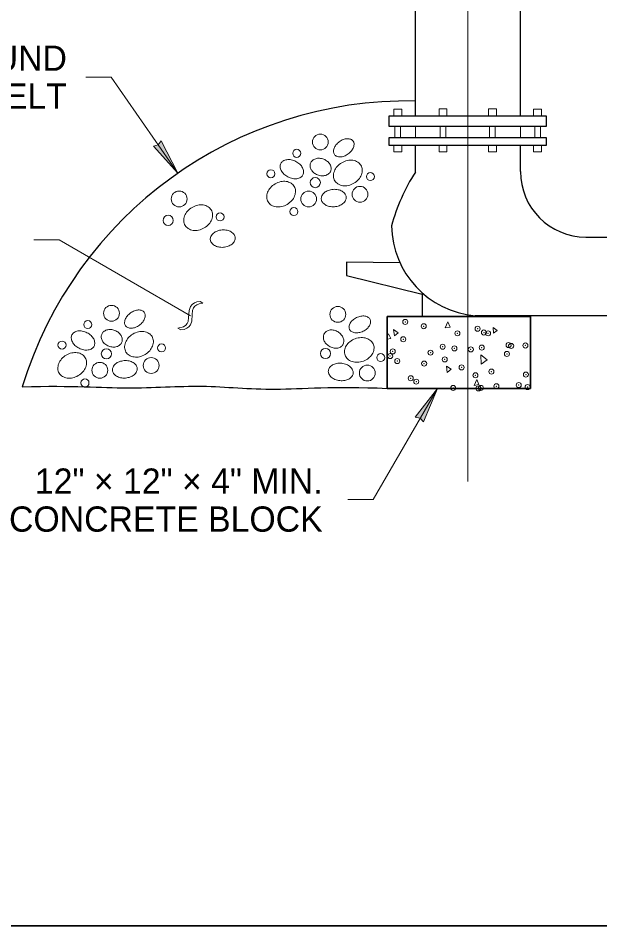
# Model space of a CAD drawing. Extents: x 99860 to 103153, y 99998 to 102077.
# Drawn here: x 101538 to 101906, y 100000 to 100574 of the extents above; entities that cross this region are included whole.
import ezdxf
from ezdxf.enums import TextEntityAlignment as Align

# ---------------------------------------------------------------- set-up
doc = ezdxf.new("R2010")
doc.units = 0
doc.header["$LTSCALE"] = 6.4
doc.header["$PDMODE"] = 32
doc.header["$PDSIZE"] = 3.2
for name, color, linetype, lineweight in [('1', 7, 'Continuous', 25), ('10', 7, 'Continuous', 13), ('15', 7, 'Continuous', 13), ('17', 7, 'Continuous', 35), ('18', 7, 'Continuous', 13), ('20', 7, 'Continuous', 13), ('6', 7, 'Continuous', 25)]:
    doc.layers.add(name, color=color, linetype=linetype, lineweight=lineweight)

msp = doc.modelspace()

# ---------------------------------------------------------------- hatches: boundary and pattern name
at = {"layer": '15'}
for points in [[(101638.764, 100475.808), (101628.184, 100496.257), (101626.336, 100493.686), (101623.282, 100492.849)], [(101803.014, 100339.647), (101794.184, 100318.384), (101792.127, 100320.791), (101789.014, 100321.369)]]:
    msp.add_hatch(color=256, dxfattribs=at).paths.add_polyline_path(points)

# ---------------------------------------------------------------- linework, layer by layer
at = {"layer": '1', "lineweight": 35}
msp.add_lwpolyline([(99862, 99999.5), (103151, 99999.5), (103151, 102075.5), (99862, 102075.5)], close=True, dxfattribs=at)
at = {"layer": '1'}
msp.add_arc((101784.759, 100265.786), 255.78, 89.02946, 162.96913, dxfattribs=at)
msp.add_open_spline([(101540.139, 100340.697), (101572.889, 100341.522), (101607.177, 100338.572), (101654.789, 100342.572), (101698.152, 100337.272), (101736.727, 100341.247), (101771.264, 100339.647)], degree=3, dxfattribs=at)
at = {"layer": '10'}
for p, q in [((101807.989, 100377.947), (101809.552, 100381.672)), ((101811.189, 100378.472), (101809.552, 100381.672)), ((101771.264, 100372.61), (101772.064, 100374.21)), ((101773.664, 100371.31), (101772.064, 100374.21)), ((101775.789, 100372.86), (101775.264, 100376.86)), ((101778.202, 100374.735), (101775.264, 100376.86)), ((101775.789, 100372.86), (101778.202, 100374.735)), ((101807.989, 100377.947), (101811.189, 100378.472)), ((101838.577, 100374.485), (101838.264, 100378.185)), ((101840.977, 100376.335), (101838.264, 100378.185)), ((101838.577, 100374.485), (101840.977, 100376.335)), ((101771.264, 100370.76), (101773.664, 100371.31)), ((101830.839, 100355.06), (101830.589, 100360.922)), ((101834.602, 100357.71), (101830.589, 100360.922)), ((101830.839, 100355.06), (101834.602, 100357.71)), ((101809.314, 100349.76), (101808.789, 100353.735)), ((101811.689, 100351.885), (101808.789, 100353.735)), ((101809.314, 100349.76), (101811.689, 100351.885)), ((101826.327, 100341.522), (101827.939, 100345.222)), ((101826.327, 100341.522), (101829.264, 100342.022)), ((101829.264, 100342.022), (101827.939, 100345.222))]:
    msp.add_line(p, q, dxfattribs=at)
for centre, radius in [((101728.919, 100495.578), 5.019), ((101713.97, 100488.402), 2.537), ((101697.625, 100475.446), 2.537), ((101725.73, 100469.865), 3.22), ((101760.613, 100473.652), 2.537), ((101754.035, 100462.489), 5.019), ((101639.54, 100459.539), 5.019), ((101721.544, 100459.5), 5.019), ((101632.564, 100445.985), 3.22), ((101665.453, 100448.178), 2.537), ((101712.176, 100451.526), 2.537), ((101596.685, 100387.184), 5.019), ((101740.01, 100386.466), 5.019), ((101581.735, 100380.008), 2.537), ((101565.39, 100367.052), 2.537), ((101593.495, 100361.471), 3.22), ((101628.378, 100365.258), 2.537), ((101732.18, 100361.767), 3.22), ((101621.8, 100354.096), 5.019), ((101767.167, 100359.122), 2.537), ((101589.309, 100351.106), 5.019), ((101758.662, 100349.348), 5.019), ((101579.941, 100343.133), 2.537)]:
    msp.add_circle(centre, radius, dxfattribs=at)
for centre, radius, start, end in [((101747.443, 100486.849), 11.024, 126.08477, 141.32523), ((101747.443, 100486.849), 11.024, 110.84431, 126.08477), ((101746.31, 100489.825), 7.839, 92.74951, 110.84431), ((101746.199, 100492.147), 5.515, 68.28483, 92.74951), ((101747.048, 100494.28), 3.219, 36.08477, 68.28483), ((101747.048, 100494.28), 3.219, 3.88471, 36.08477), ((101742.781, 100489.656), 5.515, 159.42002, 183.88471), ((101740.491, 100489.501), 3.219, 183.88471, 216.08477), ((101744.957, 100488.839), 7.839, 141.32523, 159.42002), ((101740.095, 100496.931), 11.024, 306.08477, 321.32523), ((101742.582, 100494.941), 7.839, 321.32523, 339.42002), ((101744.758, 100494.124), 5.515, 339.42002, 3.88471), ((101707.381, 100480.181), 3.917, 122.21424, 152.88878), ((101708.564, 100478.302), 6.137, 97.81622, 122.21424), ((101708.861, 100476.138), 8.322, 79.02152, 97.81622), ((101708.3, 100473.245), 11.268, 62.88878, 79.02152), ((101708.3, 100473.245), 11.268, 46.75604, 62.88878), ((101726.659, 100480.692), 4.207, 130.69622, 158.66336), ((101727.598, 100479.6), 5.648, 106.62121, 130.69622), ((101727.983, 100478.309), 6.994, 86.57049, 106.62121), ((101727.878, 100476.556), 8.751, 68.66336, 86.57049), ((101727.878, 100476.556), 8.751, 50.75623, 68.66336), ((101728.99, 100477.916), 6.994, 30.70551, 50.75623), ((101740.491, 100489.501), 3.219, 216.08477, 248.28483), ((101741.34, 100491.633), 5.515, 248.28483, 272.74951), ((101741.229, 100493.955), 7.839, 272.74951, 290.84431), ((101748.731, 100471.928), 12.202, 102.54735, 120.55568), ((101740.095, 100496.931), 11.024, 290.84431, 306.08477), ((101748.209, 100474.275), 9.798, 82.43038, 102.54735), ((101748.452, 100476.105), 7.952, 58.38014, 82.43038), ((101707.381, 100480.181), 3.917, 152.88878, 183.56332), ((101709.597, 100480.319), 6.137, 183.56332, 207.96135), ((101711.527, 100481.343), 8.322, 207.96135, 226.75604), ((101710.319, 100475.391), 8.322, 27.96135, 46.75604), ((101712.249, 100476.416), 6.137, 3.56332, 27.96135), ((101726.659, 100480.692), 4.207, 158.66336, 186.63049), ((101728.09, 100480.858), 5.648, 186.63049, 210.70551), ((101729.248, 100481.546), 6.994, 210.70551, 230.75623), ((101730.147, 100478.604), 5.648, 6.63049, 30.70551), ((101731.579, 100478.77), 4.207, 338.66336, 6.63049), ((101746.929, 100473.519), 9.798, 138.56401, 158.68099), ((101748.731, 100471.928), 12.202, 120.55568, 138.56401), ((101749.491, 100477.792), 5.971, 30.55568, 58.38014), ((101749.491, 100477.792), 5.971, 2.73122, 30.55568), ((101747.512, 100477.698), 7.952, 338.68099, 2.73122), ((101713.545, 100483.49), 11.268, 226.75604, 242.88878), ((101713.545, 100483.49), 11.268, 242.88878, 259.02152), ((101712.984, 100480.597), 8.322, 259.02152, 277.81622), ((101713.281, 100478.432), 6.137, 277.81622, 302.21424), ((101714.465, 100476.554), 3.917, 302.21424, 332.88878), ((101714.465, 100476.554), 3.917, 332.88878, 3.56332), ((101730.359, 100482.906), 8.751, 230.75623, 248.66336), ((101730.359, 100482.906), 8.751, 248.66336, 266.57049), ((101730.254, 100481.153), 6.994, 266.57049, 286.62121), ((101730.639, 100479.863), 5.648, 286.62121, 310.69623), ((101731.579, 100478.77), 4.207, 310.69623, 338.66336), ((101745.209, 100474.19), 7.952, 158.68099, 182.73122), ((101743.23, 100474.096), 5.971, 182.73122, 210.55568), ((101743.99, 100479.96), 12.202, 300.55568, 318.56401), ((101745.792, 100478.369), 9.798, 318.56401, 338.68099), ((101704.671, 100460.164), 9.798, 138.56401, 158.68099), ((101706.474, 100458.573), 12.202, 120.55568, 138.56401), ((101706.474, 100458.573), 12.202, 102.54735, 120.55568), ((101705.951, 100460.92), 9.798, 82.43038, 102.54735), ((101706.195, 100462.75), 7.952, 58.38014, 82.43038), ((101707.233, 100464.437), 5.971, 30.55568, 58.38014), ((101707.233, 100464.437), 5.971, 2.73122, 30.55568), ((101743.23, 100474.096), 5.971, 210.55568, 238.38014), ((101744.269, 100475.783), 7.952, 238.38014, 262.43038), ((101744.512, 100477.613), 9.798, 262.43038, 282.54735), ((101743.99, 100479.96), 12.202, 282.54735, 300.55568), ((101702.952, 100460.835), 7.952, 158.68099, 182.73122), ((101700.972, 100460.741), 5.971, 182.73122, 210.55568), ((101703.534, 100465.014), 9.798, 318.56401, 338.68099), ((101705.254, 100464.343), 7.952, 338.68099, 2.73122), ((101733.423, 100459.796), 3.917, 153.66865, 184.34319), ((101735.413, 100458.811), 6.137, 129.27062, 153.66865), ((101736.796, 100457.12), 8.322, 110.47593, 129.27062), ((101737.827, 100454.36), 11.268, 94.34319, 110.47593), ((101737.827, 100454.36), 11.268, 78.21045, 94.34319), ((101738.429, 100457.244), 8.322, 59.41576, 78.21045), ((101739.54, 100459.125), 6.137, 35.01773, 59.41576), ((101741.359, 100460.399), 3.917, 4.34319, 35.01773), ((101741.359, 100460.399), 3.917, 333.66865, 4.34319), ((101653.97, 100443.664), 12.202, 102.54735, 120.55568), ((101653.448, 100446.01), 9.798, 82.43038, 102.54735), ((101653.691, 100447.84), 7.952, 58.38014, 82.43038), ((101654.73, 100449.528), 5.971, 30.55568, 58.38014), ((101700.972, 100460.741), 5.971, 210.55568, 238.38014), ((101702.011, 100462.428), 7.952, 238.38014, 262.43038), ((101702.254, 100464.258), 9.798, 262.43038, 282.54735), ((101701.732, 100466.605), 12.202, 282.54735, 300.55568), ((101701.732, 100466.605), 12.202, 300.55568, 318.56401), ((101733.423, 100459.796), 3.917, 184.34319, 215.01773), ((101735.241, 100461.07), 6.137, 215.01773, 239.41576), ((101736.353, 100462.951), 8.322, 239.41576, 258.21045), ((101736.955, 100465.835), 11.268, 258.21045, 274.34319), ((101736.955, 100465.835), 11.268, 274.34319, 290.47593), ((101737.986, 100463.075), 8.322, 290.47593, 309.27062), ((101739.369, 100461.384), 6.137, 309.27062, 333.66865), ((101650.448, 100445.926), 7.952, 158.68099, 182.73122), ((101652.168, 100445.255), 9.798, 138.56401, 158.68099), ((101653.97, 100443.664), 12.202, 120.55568, 138.56401), ((101654.73, 100449.528), 5.971, 2.73122, 30.55568), ((101652.751, 100449.433), 7.952, 338.68099, 2.73122), ((101648.469, 100445.831), 5.971, 182.73122, 210.55568), ((101649.229, 100451.695), 12.202, 300.55568, 318.56401), ((101651.031, 100450.104), 9.798, 318.56401, 338.68099), ((101648.469, 100445.831), 5.971, 210.55568, 238.38014), ((101649.508, 100447.519), 7.952, 238.38014, 262.43038), ((101649.751, 100449.349), 9.798, 262.43038, 282.54735), ((101649.229, 100451.695), 12.202, 282.54735, 300.55568), ((101665.169, 100433.138), 6.137, 129.27062, 153.66865), ((101666.552, 100431.447), 8.322, 110.47593, 129.27062), ((101667.583, 100428.686), 11.268, 94.34319, 110.47593), ((101667.583, 100428.686), 11.268, 78.21045, 94.34319), ((101668.185, 100431.571), 8.322, 59.41576, 78.21045), ((101669.297, 100433.452), 6.137, 35.01773, 59.41576), ((101663.18, 100434.123), 3.917, 153.66865, 184.34319), ((101663.18, 100434.123), 3.917, 184.34319, 215.01773), ((101664.998, 100435.397), 6.137, 215.01773, 239.41576), ((101669.125, 100435.71), 6.137, 309.27062, 333.66865), ((101671.115, 100434.726), 3.917, 4.34319, 35.01773), ((101671.115, 100434.726), 3.917, 333.66865, 4.34319), ((101666.11, 100437.278), 8.322, 239.41576, 258.21045), ((101666.712, 100440.162), 11.268, 258.21045, 274.34319), ((101666.712, 100440.162), 11.268, 274.34319, 290.47593), ((101667.742, 100437.402), 8.322, 290.47593, 309.27062), ((101615.209, 100378.455), 11.024, 126.08477, 141.32523), ((101615.209, 100378.455), 11.024, 110.84431, 126.08477), ((101614.075, 100381.431), 7.839, 92.74951, 110.84431), ((101613.964, 100383.753), 5.515, 68.28483, 92.74951), ((101614.813, 100385.886), 3.219, 36.08477, 68.28483), ((101614.813, 100385.886), 3.219, 3.88471, 36.08477), ((101612.523, 100385.73), 5.515, 339.42002, 3.88471), ((101756.058, 100377.635), 7.839, 82.22884, 100.32364), ((101610.546, 100381.262), 5.515, 159.42002, 183.88471), ((101608.256, 100381.107), 3.219, 183.88471, 216.08477), ((101612.722, 100380.445), 7.839, 141.32523, 159.42002), ((101607.861, 100388.537), 11.024, 306.08477, 321.32523), ((101610.347, 100386.547), 7.839, 321.32523, 339.42002), ((101752.558, 100378.113), 5.515, 148.89935, 173.36404), ((101754.548, 100376.912), 7.839, 130.80456, 148.89936), ((101756.629, 100374.502), 11.024, 115.5641, 130.80456), ((101756.629, 100374.502), 11.024, 100.32364, 115.5641), ((101756.373, 100379.938), 5.515, 57.76416, 82.22884), ((101757.597, 100381.879), 3.219, 25.5641, 57.76416), ((101755.317, 100382.145), 5.515, 328.89935, 353.36404), ((101757.597, 100381.879), 3.219, 353.36404, 25.5641), ((101575.146, 100371.787), 3.917, 122.21424, 152.88878), ((101576.33, 100369.909), 6.137, 97.81622, 122.21424), ((101576.627, 100367.744), 8.322, 79.02152, 97.81622), ((101576.066, 100364.852), 11.268, 62.88878, 79.02152), ((101576.066, 100364.852), 11.268, 46.75604, 62.88878), ((101594.424, 100372.298), 4.207, 130.69622, 158.66336), ((101595.364, 100371.206), 5.648, 106.62121, 130.69622), ((101595.749, 100369.916), 6.994, 86.57049, 106.62121), ((101595.644, 100368.162), 8.751, 68.66336, 86.57049), ((101595.644, 100368.162), 8.751, 50.75623, 68.66336), ((101596.755, 100369.523), 6.994, 30.70551, 50.75623), ((101608.256, 100381.107), 3.219, 216.08477, 248.28483), ((101609.105, 100383.24), 5.515, 248.28483, 272.74951), ((101616.497, 100363.534), 12.202, 120.55568, 138.56401), ((101608.994, 100385.561), 7.839, 272.74951, 290.84431), ((101616.497, 100363.534), 12.202, 102.54735, 120.55568), ((101607.861, 100388.537), 11.024, 290.84431, 306.08477), ((101615.974, 100365.881), 9.798, 82.43038, 102.54735), ((101616.218, 100367.711), 7.952, 58.38014, 82.43038), ((101617.256, 100369.398), 5.971, 30.55568, 58.38014), ((101735.07, 100372.243), 4.207, 148.14269, 176.10982), ((101735.07, 100372.243), 4.207, 120.17556, 148.14269), ((101735.794, 100370.998), 5.648, 96.10054, 120.17556), ((101735.937, 100369.659), 6.994, 76.04982, 96.10054), ((101735.514, 100367.954), 8.751, 58.14269, 76.04982), ((101735.514, 100367.954), 8.751, 40.23556, 58.14269), ((101750.278, 100378.378), 3.219, 173.36404, 205.5641), ((101750.278, 100378.378), 3.219, 205.5641, 237.76416), ((101751.502, 100380.32), 5.515, 237.76416, 262.22884), ((101751.816, 100382.623), 7.839, 262.22884, 280.32364), ((101751.246, 100385.756), 11.024, 280.32364, 295.5641), ((101751.246, 100385.756), 11.024, 295.5641, 310.80456), ((101753.327, 100383.345), 7.839, 310.80456, 328.89936), ((101575.146, 100371.787), 3.917, 152.88878, 183.56332), ((101577.362, 100371.925), 6.137, 183.56332, 207.96135), ((101579.292, 100372.95), 8.322, 207.96135, 226.75604), ((101578.084, 100366.998), 8.322, 27.96135, 46.75604), ((101580.014, 100368.022), 6.137, 3.56332, 27.96135), ((101582.23, 100368.16), 3.917, 332.88878, 3.56332), ((101594.424, 100372.298), 4.207, 158.66336, 186.63049), ((101595.855, 100372.465), 5.648, 186.63049, 210.70551), ((101597.013, 100373.152), 6.994, 210.70551, 230.75623), ((101599.344, 100370.376), 4.207, 310.69623, 338.66336), ((101597.913, 100370.21), 5.648, 6.63049, 30.70551), ((101599.344, 100370.376), 4.207, 338.66336, 6.63049), ((101612.975, 100365.797), 7.952, 158.68099, 182.73122), ((101614.694, 100365.125), 9.798, 138.56401, 158.68099), ((101617.256, 100369.398), 5.971, 2.73122, 30.55568), ((101615.277, 100369.304), 7.952, 338.68099, 2.73122), ((101736.508, 100372.146), 5.648, 176.10983, 200.18484), ((101737.771, 100372.61), 6.994, 200.18484, 220.23556), ((101736.855, 100369.089), 6.994, 20.18484, 40.23556), ((101739.556, 100369.455), 4.207, 328.14269, 356.10982), ((101738.118, 100369.553), 5.648, 356.10983, 20.18484), ((101753.69, 100361.49), 9.798, 128.04334, 148.16032), ((101755.171, 100359.597), 12.202, 110.03501, 128.04334), ((101755.171, 100359.597), 12.202, 92.02668, 110.03501), ((101755.086, 100361.999), 9.798, 71.90971, 92.02668), ((101755.659, 100363.754), 7.952, 47.85948, 71.90971), ((101756.989, 100365.223), 5.971, 20.03501, 47.85948), ((101581.31, 100375.096), 11.268, 226.75604, 242.88878), ((101581.31, 100375.096), 11.268, 242.88878, 259.02152), ((101580.749, 100372.203), 8.322, 259.02152, 277.81622), ((101581.046, 100370.039), 6.137, 277.81622, 302.21424), ((101582.23, 100368.16), 3.917, 302.21424, 332.88878), ((101598.124, 100374.513), 8.751, 230.75623, 248.66336), ((101598.124, 100374.513), 8.751, 248.66336, 266.57049), ((101598.019, 100372.759), 6.994, 266.57049, 286.62121), ((101598.404, 100371.469), 5.648, 286.62121, 310.69623), ((101610.995, 100365.702), 5.971, 182.73122, 210.55568), ((101610.995, 100365.702), 5.971, 210.55568, 238.38014), ((101611.755, 100371.566), 12.202, 300.55568, 318.56401), ((101613.557, 100369.975), 9.798, 318.56401, 338.68099), ((101739.112, 100373.745), 8.751, 220.23556, 238.14269), ((101739.112, 100373.745), 8.751, 238.14269, 256.04982), ((101738.689, 100372.04), 6.994, 256.04982, 276.10054), ((101738.832, 100370.701), 5.648, 276.10054, 300.17556), ((101739.556, 100369.455), 4.207, 300.17556, 328.14269), ((101750.158, 100362.732), 5.971, 172.21055, 200.03501), ((101752.121, 100362.464), 7.952, 148.16032, 172.21055), ((101755.026, 100365.492), 7.952, 328.16032, 352.21055), ((101756.989, 100365.223), 5.971, 352.21055, 20.03501), ((101572.437, 100351.77), 9.798, 138.56401, 158.68099), ((101574.239, 100350.18), 12.202, 120.55568, 138.56401), ((101574.239, 100350.18), 12.202, 102.54735, 120.55568), ((101573.717, 100352.526), 9.798, 82.43038, 102.54735), ((101573.96, 100354.356), 7.952, 58.38014, 82.43038), ((101574.999, 100356.043), 5.971, 30.55568, 58.38014), ((101574.999, 100356.043), 5.971, 2.73122, 30.55568), ((101605.592, 100345.966), 11.268, 94.34319, 110.47593), ((101605.592, 100345.966), 11.268, 78.21045, 94.34319), ((101612.034, 100367.389), 7.952, 238.38014, 262.43038), ((101606.194, 100348.85), 8.322, 59.41576, 78.21045), ((101612.277, 100369.219), 9.798, 262.43038, 282.54735), ((101611.755, 100371.566), 12.202, 282.54735, 300.55568), ((101750.158, 100362.732), 5.971, 200.03501, 227.85948), ((101751.488, 100364.201), 7.952, 227.85948, 251.90971), ((101751.976, 100368.359), 12.202, 272.02668, 290.03501), ((101751.976, 100368.359), 12.202, 290.03501, 308.04334), ((101753.457, 100366.465), 9.798, 308.04334, 328.16032), ((101570.717, 100352.442), 7.952, 158.68099, 182.73122), ((101568.738, 100352.347), 5.971, 182.73122, 210.55568), ((101571.3, 100356.62), 9.798, 318.56401, 338.68099), ((101573.02, 100355.949), 7.952, 338.68099, 2.73122), ((101601.188, 100351.402), 3.917, 153.66865, 184.34319), ((101601.188, 100351.402), 3.917, 184.34319, 215.01773), ((101603.178, 100350.418), 6.137, 129.27062, 153.66865), ((101604.561, 100348.726), 8.322, 110.47593, 129.27062), ((101607.306, 100350.731), 6.137, 35.01773, 59.41576), ((101609.124, 100352.005), 3.917, 4.34319, 35.01773), ((101609.124, 100352.005), 3.917, 333.66865, 4.34319), ((101737.905, 100350.464), 3.917, 143.14798, 173.82252), ((101739.682, 100349.132), 6.137, 118.74996, 143.14798), ((101740.733, 100347.216), 8.322, 99.95526, 118.74996), ((101741.242, 100344.314), 11.268, 83.82252, 99.95526), ((101741.242, 100344.314), 11.268, 67.68978, 83.82252), ((101742.36, 100347.04), 8.322, 48.89509, 67.68978), ((101743.797, 100348.687), 6.137, 24.49706, 48.89509), ((101752.061, 100365.956), 9.798, 251.90971, 272.02668), ((101745.817, 100349.607), 3.917, 353.82252, 24.49706), ((101568.738, 100352.347), 5.971, 210.55568, 238.38014), ((101569.777, 100354.034), 7.952, 238.38014, 262.43038), ((101570.02, 100355.864), 9.798, 262.43038, 282.54735), ((101569.497, 100358.211), 12.202, 282.54735, 300.55568), ((101569.497, 100358.211), 12.202, 300.55568, 318.56401), ((101603.007, 100352.676), 6.137, 215.01773, 239.41576), ((101604.118, 100354.557), 8.322, 239.41576, 258.21045), ((101604.72, 100357.442), 11.268, 258.21045, 274.34319), ((101604.72, 100357.442), 11.268, 274.34319, 290.47593), ((101605.751, 100354.681), 8.322, 290.47593, 309.27062), ((101607.134, 100352.99), 6.137, 309.27062, 333.66865), ((101737.905, 100350.464), 3.917, 173.82252, 204.49706), ((101739.925, 100351.384), 6.137, 204.49706, 228.89509), ((101741.362, 100353.031), 8.322, 228.89509, 247.68978), ((101742.48, 100355.756), 11.268, 247.68978, 263.82252), ((101742.99, 100352.854), 8.322, 279.95526, 298.74996), ((101744.041, 100350.939), 6.137, 298.74996, 323.14798), ((101745.817, 100349.607), 3.917, 323.14798, 353.82252), ((101742.48, 100355.756), 11.268, 263.82252, 279.95526)]:
    msp.add_arc(centre, radius, start, end, dxfattribs=at)
for p in [(101782.702, 100381.672), (101794.414, 100378.997), (101815.689, 100374.485), (101828.464, 100377.422), (101832.464, 100375.01), (101835.089, 100374.485), (101781.402, 100370.76), (101848.139, 100367.06), (101858.777, 100366.785), (101774.739, 100363.047), (101798.677, 100362.247), (101806.377, 100365.985), (101813.814, 100364.935), (101824.202, 100364.347), (101831.114, 100365.422), (101847.089, 100361.447), (101849.739, 100366.51), (101773.139, 100360.085), (101777.639, 100356.91), (101794.664, 100355.347), (101807.702, 100357.997), (101818.352, 100352.935), (101837.214, 100350.285), (101786.152, 100346.035), (101789.639, 100343.897), (101827.139, 100347.91), (101859.052, 100348.397), (101813.039, 100339.897), (101828.989, 100339.647), (101830.589, 100339.897), (101840.427, 100340.972), (101854.514, 100341.772), (101860.127, 100340.447)]:
    msp.add_point(p, dxfattribs=at)
at = {"layer": '15'}
for p, q in [((101822.327, 101138.385), (101822.327, 100280.712)), ((101580.495, 100536.614), (101596.495, 100536.614)), ((101638.764, 100475.808), (101596.495, 100536.614)), ((101547.598, 100433.63), (101563.598, 100433.63)), ((101646.695, 100385.654), (101563.598, 100433.63)), ((101803.014, 100339.647), (101762.389, 100269.283)), ((101746.389, 100269.283), (101762.389, 100269.283))]:
    msp.add_line(p, q, dxfattribs=at)
for points in [[(101638.764, 100475.808), (101628.184, 100496.257), (101626.336, 100493.686), (101623.282, 100492.849)], [(101803.014, 100339.647), (101794.184, 100318.384), (101792.127, 100320.791), (101789.014, 100321.369)]]:
    msp.add_lwpolyline(points, close=True, dxfattribs=at)
at = {"layer": '17'}
msp.add_lwpolyline([(101771.264, 100339.647), (101771.264, 100385.135), (101861.977, 100385.135), (101861.977, 100339.647)], close=True, dxfattribs=at)
at = {"layer": '18'}
for p, q in [((101775.489, 100516.335), (101780.452, 100516.335)), ((101775.489, 100511.96), (101775.489, 100516.335)), ((101780.452, 100511.96), (101780.452, 100516.335)), ((101804.127, 100516.46), (101809.089, 100516.46)), ((101804.127, 100512.047), (101804.127, 100516.46)), ((101809.089, 100512.047), (101809.089, 100516.46)), ((101835.402, 100516.46), (101840.364, 100516.46)), ((101835.402, 100512.047), (101835.402, 100516.46)), ((101840.364, 100512.047), (101840.364, 100516.46)), ((101863.989, 100516.397), (101868.952, 100516.397)), ((101863.989, 100511.985), (101863.989, 100516.397)), ((101868.952, 100511.985), (101868.952, 100516.397)), ((101776.189, 100498.147), (101776.189, 100505.61)), ((101779.739, 100498.147), (101779.739, 100505.61)), ((101804.839, 100498.147), (101804.839, 100505.61)), ((101808.389, 100498.147), (101808.389, 100505.61)), ((101836.102, 100498.147), (101836.102, 100505.61)), ((101839.652, 100498.147), (101839.652, 100505.61)), ((101864.689, 100498.147), (101864.689, 100505.61)), ((101868.239, 100498.147), (101868.239, 100505.61)), ((101775.489, 100493.647), (101775.489, 100489.26)), ((101775.489, 100489.26), (101780.452, 100489.26)), ((101780.452, 100493.647), (101780.452, 100489.26)), ((101804.127, 100493.647), (101804.127, 100489.26)), ((101804.127, 100489.26), (101809.089, 100489.26)), ((101809.089, 100493.647), (101809.089, 100489.26)), ((101835.402, 100493.647), (101835.402, 100489.26)), ((101835.402, 100489.26), (101840.364, 100489.26)), ((101840.364, 100493.647), (101840.364, 100489.26)), ((101863.989, 100493.647), (101863.989, 100489.26)), ((101863.989, 100489.26), (101868.952, 100489.26)), ((101868.952, 100493.647), (101868.952, 100489.26))]:
    msp.add_line(p, q, dxfattribs=at)
at = {"layer": '18', "lineweight": 25}
for p, q in [((101789.077, 100476.347), (101789.077, 100493.647)), ((101855.602, 100476.872), (101855.602, 100493.647)), ((101897.077, 100435.397), (101922.389, 100435.397)), ((101922.389, 100385.622), (101826.888, 100385.622))]:
    msp.add_line(p, q, dxfattribs=at)
for points in [[(101872.064, 100505.61), (101872.064, 100511.985), (101772.339, 100511.985), (101772.339, 100505.61)], [(101872.064, 100493.647), (101872.064, 100498.147), (101772.339, 100498.147), (101772.339, 100493.647)]]:
    msp.add_lwpolyline(points, close=True, dxfattribs=at)
msp.add_lwpolyline([(101779.277, 100419.172), (101745.477, 100419.422), (101745.477, 100411.16), (101793.339, 100399.222), (101793.339, 100385.135)], dxfattribs=at)
for centre, radius, start, end in [((101886.361, 100413.162), 116.048, 146.94936, 165.35136), ((101897.138, 100476.958), 41.557, 180, 270), ((101831.863, 100443.189), 57.782, 180.67379, 265.06119)]:
    msp.add_arc(centre, radius, start, end, dxfattribs=at)
at = {"layer": '20'}
for points in [[(101643.77, 100379.555), (101642.373, 100378.684), (101638.81, 100377.701), (101640.641, 100376.644), (101642.757, 100377.005), (101644.416, 100377.649), (101645.718, 100378.607), (101646.721, 100379.932), (101647.615, 100382.23), (101647.879, 100386.312), (101648.105, 100388.854), (101648.737, 100390.666), (101649.559, 100391.716), (101650.657, 100392.521), (101652.277, 100393.142), (101654.646, 100393.659), (101652.816, 100394.716)], [(101652.816, 100394.715), (101650.844, 100394.461), (101649.168, 100393.828), (101647.797, 100392.811), (101646.726, 100391.412), (101645.797, 100388.855), (101645.425, 100384.459), (101645.221, 100382.044), (101644.69, 100380.64), (101643.77, 100379.555)]]:
    msp.add_lwpolyline(points, dxfattribs=at)
at = {"layer": '6'}
for p, q in [((101789.077, 100511.985), (101789.077, 100802.41)), ((101855.602, 100511.985), (101855.602, 100802.41))]:
    msp.add_line(p, q, dxfattribs=at)
at = {"layer": '6', "lineweight": 13}
for p, q in [((101789.077, 100498.147), (101789.077, 100505.61)), ((101855.602, 100498.147), (101855.602, 100505.61))]:
    msp.add_line(p, q, dxfattribs=at)

# ---------------------------------------------------------------- texts
at = {"layer": '20'}
for s, p in [('15 POUND', (101568.505, 100540.614)), ('ASPHALTIC FELT', (101568.505, 100516.614)), ('12" × 12" × 4" MIN.', (101730.389, 100272.945)), ('CONCRETE BLOCK', (101730.389, 100248.945))]:
    msp.add_text(s, height=16, dxfattribs=at).set_placement(p, align=Align.RIGHT)

doc.saveas('drawing.dxf')
